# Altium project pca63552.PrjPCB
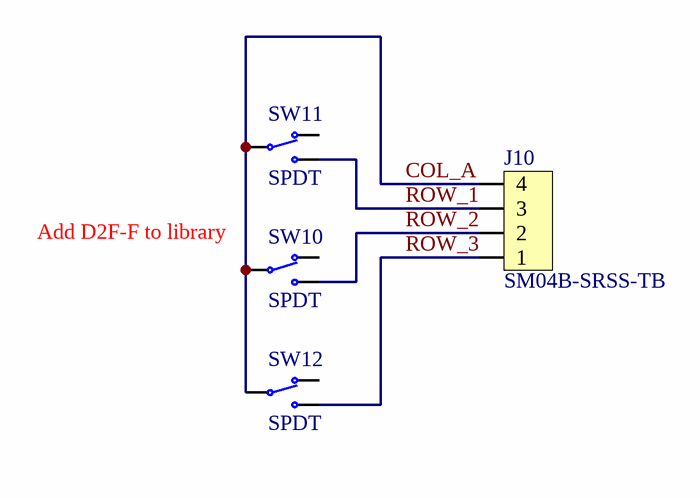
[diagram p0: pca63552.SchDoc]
SurfaceFinish: Lead-Free HASL; SoldermaskColor: Blue; SilkscreenColor: White; Revision: 0.1.0; ProjectNumber: 4456; ProjectName: nRF52 Desktop; PCBStackup: 4001; PCBRevision: 0305RUBR; PCBNumber: 400396; PCAName: PCA63552; Organization: Nordic Semiconductor; NrOfLayers: 4; BoardTitle: nRF52840 Gaming Mouse Left Buttons Board; BoardThickness: 1.6mm; Author: RUBR
1 sheet, 4 parts. Net scope: global (net labels, ports and power ports of the same name join across sheets).
Board file: 400396.PcbDoc

## Sheet pca63552.SchDoc: =BoardTitle
size A4; Organization: Nordic Semiconductor; Revision: 0.1.0; SheetNumber: 1; SheetTotal: 1; Author: RUBR; CompanyName: Nordic Semiconductor; DrawnBy: RUBR

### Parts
J10  SM04B-SRSS-TB  [SM04B-SRSS-TB]
SW10  SPDT  [SS0750300F130P1A]
SW11  SPDT  [SS0750300F130P1A]
SW12  SPDT  [SS0750300F130P1A]

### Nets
COL_A: J10.4 SW10.2(COM) SW11.2(COM) SW12.2(COM)
ROW_1: J10.3 SW11.3(N.O)
ROW_2: J10.2 SW10.3(N.O)
ROW_3: J10.1 SW12.3(N.O)

Not connected (* = marked no-connect by the designer): SW10 1(N.C); SW11 1(N.C); SW12 1(N.C)

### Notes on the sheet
- (near SW10) Add D2F-F to library

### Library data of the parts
J10 = SM04B-SRSS-TB: JST SR/SH 1.0mm 4-pin; Manufacturer: JST Sales America Inc.; Artikkelnr Noca: N.A.
SW10-SW12 = SS0750300F130P1A: Sub-miniature snap action switch; Part Number: D2F-F; Manufacturer: Omron; Part number IPS: N.A.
